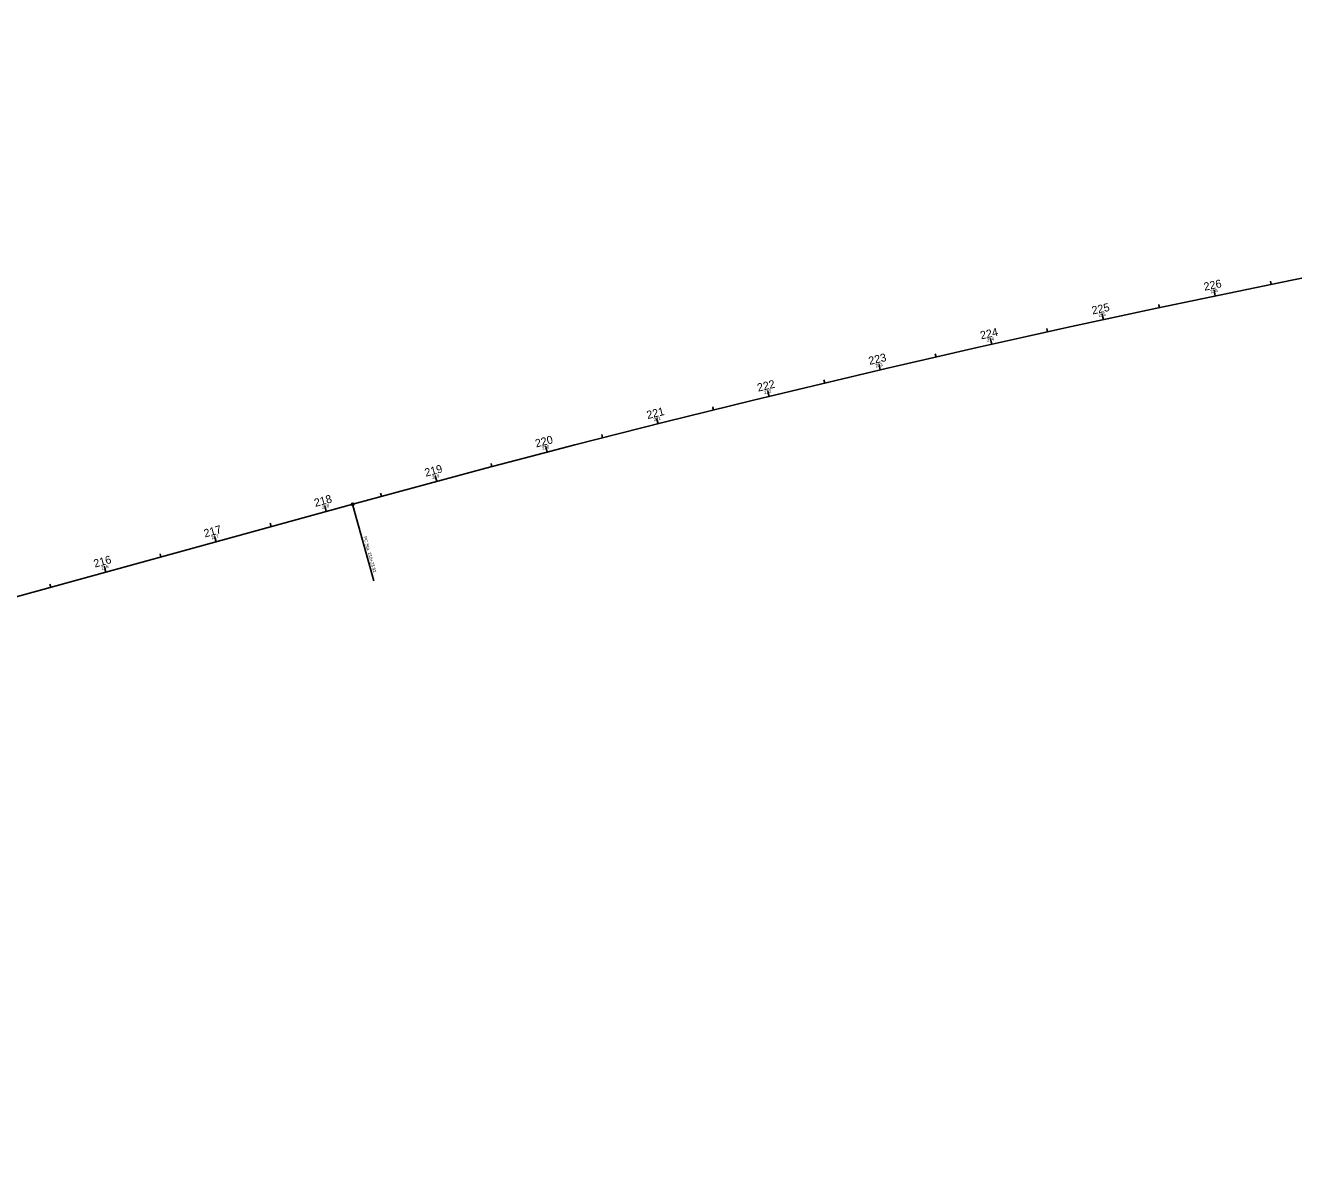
# Model space of a CAD drawing. Extents: x 2129507 to 2138391, y 657622 to 659877.
# Drawn here: x 2135058 to 2136167, y 658726 to 659734 of the extents above; entities that cross this region are included whole.
import ezdxf

# ---------------------------------------------------------------- set-up
doc = ezdxf.new("R2010")
doc.units = 0
for name, color, linetype in [('Default', 7, 'Continuous'), ('GE_X_Alignment_1000_Stations', 7, 'Continuous'), ('GE_X_Alignment_100_Stations', 7, 'Continuous'), ('GE_X_Alignment_500_Stations', 7, 'Continuous'), ('GE_X_CL_20', 7, 'Continuous'), ('MT_P_CL_20', 7, 'Continuous')]:
    doc.layers.add(name, color=color, linetype=linetype)

msp = doc.modelspace()

# ---------------------------------------------------------------- linework, layer by layer
at = {"layer": 'Default'}
for centre in [(2136098.8, 659497.9), (2136001, 659477.1), (2136001, 659477.1), (2135903.4, 659455.5), (2135805.9, 659433.1), (2135708.6, 659409.9), (2135611.6, 659386), (2135514.7, 659361.2), (2135514.7, 659361.2), (2135514.7, 659361.2), (2135418, 659335.7), (2135344.6, 659315.7), (2135344.6, 659315.7), (2135344.6, 659315.7), (2135321.5, 659309.4), (2135225.1, 659282.8), (2135128.7, 659256.3)]:
    msp.add_circle(centre, 0.0000833, dxfattribs=at)
at = {"layer": 'GE_X_Alignment_1000_Stations'}
for p, q in [((2136001, 659477.1), (2136000.4, 659480)), ((2135514.7, 659361.2), (2135513.4, 659366.1))]:
    msp.add_line(p, q, dxfattribs=at)
at = {"layer": 'GE_X_Alignment_100_Stations'}
for p, q in [((2136147.8, 659508), (2136147.2, 659510.9)), ((2136098.8, 659497.9), (2136097.8, 659502.8)), ((2136049.9, 659487.6), (2136049.3, 659490.5)), ((2136001, 659477.1), (2136000, 659482)), ((2135952.2, 659466.4), (2135951.5, 659469.3)), ((2135903.4, 659455.5), (2135902.3, 659460.4)), ((2135854.6, 659444.4), (2135854, 659447.3)), ((2135805.9, 659433.1), (2135804.8, 659438)), ((2135757.3, 659421.6), (2135756.6, 659424.5)), ((2135708.6, 659409.9), (2135707.5, 659414.8)), ((2135660.1, 659398.1), (2135659.4, 659401)), ((2135611.6, 659386), (2135610.3, 659390.8)), ((2135563.1, 659373.7), (2135562.3, 659376.6)), ((2135514.7, 659361.2), (2135513.4, 659366.1)), ((2135466.3, 659348.5), (2135465.5, 659351.4)), ((2135418, 659335.7), (2135416.7, 659340.5)), ((2135369.7, 659322.6), (2135368.9, 659325.5)), ((2135321.5, 659309.4), (2135320.2, 659314.2)), ((2135273.3, 659296.1), (2135272.5, 659299)), ((2135225.1, 659282.8), (2135223.8, 659287.6)), ((2135176.9, 659269.6), (2135176.1, 659272.4)), ((2135128.7, 659256.3), (2135127.4, 659261.1)), ((2135080.5, 659243), (2135079.7, 659245.9))]:
    msp.add_line(p, q, dxfattribs=at)
at = {"layer": 'GE_X_Alignment_500_Stations'}
for p, q in [((2136098.8, 659497.9), (2136098.2, 659500.8)), ((2136001, 659477.1), (2136000, 659482)), ((2135903.4, 659455.5), (2135902.7, 659458.4)), ((2135805.9, 659433.1), (2135805.2, 659436)), ((2135708.6, 659409.9), (2135707.9, 659412.9)), ((2135611.6, 659386), (2135610.8, 659388.9)), ((2135514.7, 659361.2), (2135513.4, 659366.1)), ((2135418, 659335.7), (2135417.2, 659338.6)), ((2135321.5, 659309.4), (2135320.7, 659312.3)), ((2135225.1, 659282.8), (2135224.3, 659285.7)), ((2135128.7, 659256.3), (2135127.9, 659259.2))]:
    msp.add_line(p, q, dxfattribs=at)
at = {"layer": 'GE_X_CL_20'}
for p, q in [((2136098.8, 659497.9), (2136098.4, 659499.8)), ((2136147.8, 659508), (2136147.4, 659509.9)), ((2136049.9, 659487.6), (2136049.5, 659489.5)), ((2136001, 659477.1), (2136000.6, 659479)), ((2135952.2, 659466.4), (2135951.7, 659468.3)), ((2135903.4, 659455.5), (2135902.9, 659457.4)), ((2135854.6, 659444.4), (2135854.2, 659446.4)), ((2135805.9, 659433.1), (2135805.5, 659435.1)), ((2135757.3, 659421.6), (2135756.8, 659423.6)), ((2135708.6, 659409.9), (2135708.2, 659411.9)), ((2135660.1, 659398.1), (2135659.6, 659400)), ((2135611.6, 659386), (2135611.1, 659387.9)), ((2135563.1, 659373.7), (2135562.6, 659375.6)), ((2135514.7, 659361.2), (2135514.2, 659363.1)), ((2135466.3, 659348.5), (2135465.8, 659350.5)), ((2135418, 659335.7), (2135417.5, 659337.6)), ((2135369.7, 659322.6), (2135369.2, 659324.5)), ((2129536.9, 657717.3), (2135344.6, 659315.7)), ((2135321.5, 659309.4), (2135321, 659311.3)), ((2135344.8, 659314.7), (2135363, 659248.7)), ((2135273.3, 659296.1), (2135272.8, 659298)), ((2135225.1, 659282.8), (2135224.6, 659284.8)), ((2135176.9, 659269.6), (2135176.4, 659271.5)), ((2135128.7, 659256.3), (2135128.1, 659258.2)), ((2135080.5, 659243), (2135079.9, 659244.9))]:
    msp.add_line(p, q, dxfattribs=at)
msp.add_circle((2135344.6, 659315.7), 1, dxfattribs=at)
msp.add_arc((2138602.6, 647478.2), 12277.7, 93.38277, 105.38861, dxfattribs=at)
at = {"layer": 'MT_P_CL_20'}
msp.add_line((2129536.9, 657717.3), (2135344.6, 659315.7), dxfattribs=at)
msp.add_arc((2138602.6, 647478.2), 12277.7, 93.38277, 105.38861, dxfattribs=at)

# ---------------------------------------------------------------- texts
at = {"layer": 'GE_X_Alignment_1000_Stations'}
msp.add_text('220', height=7, rotation=14.5669, dxfattribs=at).set_placement((2135505.1, 659365.3))
at = {"layer": 'GE_X_Alignment_100_Stations'}
for s, rotation, p in [('226', 11.7669, (2136089.5, 659502.4)), ('225', 12.2335, (2135991.6, 659481.6)), ('224', 12.7002, (2135894.1, 659459.8)), ('223', 13.1669, (2135796.5, 659437.5)), ('222', 13.6335, (2135699.2, 659414.1)), ('221', 14.1002, (2135602.5, 659390.1)), ('220', 14.5669, (2135505.1, 659365.3)), ('219', 15.0335, (2135408.5, 659339.7)), ('218', 15.3886, (2135311.9, 659313.3)), ('217', 15.3886, (2135215.4, 659286.6)), ('216', 15.3886, (2135119.1, 659260.2))]:
    msp.add_text(s, height=7, rotation=rotation, dxfattribs=at).set_placement(p)
at = {"layer": 'GE_X_Alignment_500_Stations'}
for s, rotation, p in [('225', 12.2335, (2135991.6, 659481.6)), ('220', 14.5669, (2135505.1, 659365.3))]:
    msp.add_text(s, height=7, rotation=rotation, dxfattribs=at).set_placement(p)
at = {"layer": 'GE_X_CL_20'}
for s, rotation, p in [('226', 11.7669, (2136094.8, 659500.1)), ('225', 12.2335, (2135997, 659479.3)), ('224', 12.7002, (2135899.4, 659457.7)), ('223', 13.1669, (2135801.9, 659435.2)), ('222', 13.6335, (2135704.6, 659412)), ('221', 14.1002, (2135608, 659388.2)), ('220', 14.5669, (2135510.5, 659363.2)), ('219', 15.0335, (2135414.4, 659337.8)), ('218', 15.3886, (2135318, 659311.5)), ('217', 15.3886, (2135221.4, 659284.9)), ('PC Sta. 218+23.92', 285.3886, (2135353.9, 659287.2)), ('216', 15.3886, (2135125.1, 659258.4))]:
    msp.add_text(s, height=2.8, rotation=rotation, dxfattribs=at).set_placement(p)

doc.saveas('drawing.dxf')
